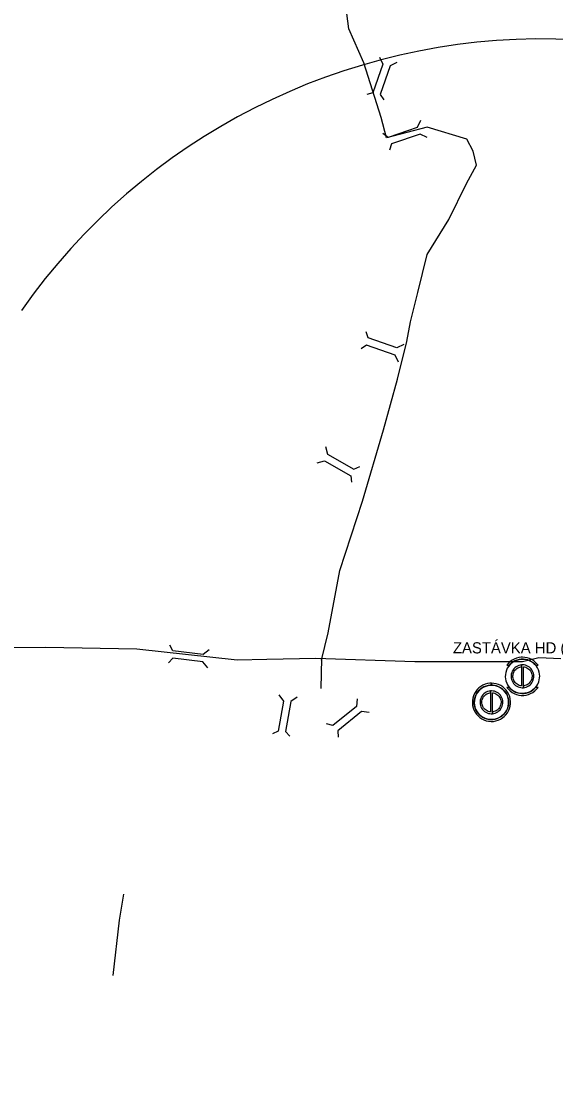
# Model space of a CAD drawing. Extents: x -520790 to -517278, y -1190021 to -1185077.
# Drawn here: x -519098 to -518762, y -1187441 to -1186765 of the extents above; entities that cross this region are included whole.
import ezdxf

# ---------------------------------------------------------------- set-up
doc = ezdxf.new("R2010")
doc.units = 0
for name, color, linetype in [('cyklostezka_n', 7, 'Continuous'), ('cyklostezka_s', 7, 'Continuous'), ('dostupnost_s', 7, 'Continuous'), ('most_s', 7, 'Continuous'), ('stezka_s', 7, 'Continuous'), ('zast_HD_n', 7, 'Continuous'), ('zast_HD_s', 7, 'Continuous')]:
    doc.layers.add(name, color=color, linetype=linetype)

msp = doc.modelspace()

# ---------------------------------------------------------------- linework, layer by layer
at = {"layer": 'cyklostezka_n'}
msp.add_lwpolyline([(-518909.06, -1187166.39), (-518904.87, -1187149.27), (-518897.53, -1187110.14), (-518883.2, -1187066.46), (-518870.1, -1187021.73), (-518861.36, -1186989.94), (-518855.42, -1186966.18), (-518853.15, -1186953.95), (-518848.44, -1186935.43), (-518842.67, -1186911.67), (-518829.04, -1186889.65), (-518817.86, -1186866.94), (-518811.57, -1186855.41), (-518813.67, -1186846.67), (-518817.7, -1186839.01), (-518842.67, -1186831.65), (-518868.09, -1186838.24), (-518871.57, -1186825.5), (-518882.5, -1186791.12), (-518891.94, -1186769.8), (-518895.08, -1186745.52)], dxfattribs=at)
at = {"layer": 'cyklostezka_s'}
msp.add_lwpolyline([(-519148.5, -1187158.48), (-519082.51, -1187158.33), (-519025.1, -1187159.41), (-518962.02, -1187166.21), (-518943.49, -1187165.91), (-518912.67, -1187165.14), (-518850.44, -1187167.37), (-518782.75, -1187167.37), (-518772.35, -1187164.69), (-518758.64, -1187165.51)], dxfattribs=at)
at = {"layer": 'dostupnost_s'}
for centre, start, end in [((-518769.97, -1187176.11), 32.65634, 144.99756), ((-519122.18, -1187345.91), 185.51814, 324.99756)]:
    msp.add_arc(centre, 400, start, end, dxfattribs=at)
at = {"layer": 'most_s'}
for points in [[(-518872.6, -1186787.54), (-518870.47, -1186791.9), (-518876.69, -1186809.95), (-518880.6, -1186811.14)], [(-518861.59, -1186790.87), (-518865.97, -1186792.97), (-518872.26, -1186811), (-518869.93, -1186814.34)], [(-518846.89, -1186827.35), (-518849, -1186831.72), (-518867.05, -1186837.97), (-518870.39, -1186835.63)], [(-518842.71, -1186838.07), (-518847.06, -1186835.92), (-518865.13, -1186842.1), (-518866.33, -1186846)], [(-518857.3, -1186968.12), (-518861.65, -1186970.26), (-518879.71, -1186964.03), (-518880.89, -1186960.13)], [(-518860.62, -1186979.13), (-518862.72, -1186974.76), (-518880.75, -1186968.46), (-518884.1, -1186970.8)], [(-518906.54, -1187032.27), (-518905.29, -1187036.95), (-518888.74, -1187046.49), (-518885.01, -1187044.81)], [(-518911.85, -1187042.47), (-518907.17, -1187041.18), (-518890.58, -1187050.65), (-518890.15, -1187054.71)], [(-518979.66, -1187159.89), (-518983.46, -1187162.9), (-519002.43, -1187160.65), (-519004.41, -1187157.08)], [(-518980.57, -1187171.35), (-518983.55, -1187167.52), (-519002.5, -1187165.2), (-519005.28, -1187168.19)], [(-518935.82, -1187188.23), (-518933.01, -1187192.18), (-518936.24, -1187211), (-518939.91, -1187212.8)], [(-518924.42, -1187189.73), (-518928.4, -1187192.51), (-518931.7, -1187211.32), (-518928.86, -1187214.24)], [(-518886.65, -1187190.68), (-518887.14, -1187195.51), (-518901.95, -1187207.56), (-518905.89, -1187206.5)], [(-518879.05, -1187199.32), (-518883.87, -1187198.79), (-518898.74, -1187210.78), (-518898.52, -1187214.86)]]:
    msp.add_lwpolyline(points, dxfattribs=at)
at = {"layer": 'stezka_s'}
for points in [[(-518909, -1187165.33), (-518909.41, -1187184.23), (-518909.41, -1187184.23)], [(-519039.9, -1187364.57), (-519036.07, -1187329.87), (-519033.21, -1187313.42)]]:
    msp.add_lwpolyline(points, dxfattribs=at)
at = {"layer": 'zast_HD_n'}
msp.add_line((-518782.09, -1187183.76), (-518782.09, -1187183.76), dxfattribs=at)
for points in [[(-518771.89, -1187176.6), (-518771.98, -1187175.23), (-518772.24, -1187173.89), (-518772.66, -1187172.59), (-518773.25, -1187171.36), (-518773.98, -1187170.21), (-518774.86, -1187169.16), (-518775.86, -1187168.23), (-518776.97, -1187167.43), (-518778.17, -1187166.78), (-518779.45, -1187166.29), (-518780.77, -1187165.96), (-518782.13, -1187165.81), (-518783.5, -1187165.82), (-518784.85, -1187166.01), (-518786.17, -1187166.36), (-518787.43, -1187166.88), (-518788.62, -1187167.56), (-518789.72, -1187168.38), (-518790.7, -1187169.33), (-518791.55, -1187170.4), (-518792.26, -1187171.56), (-518792.82, -1187172.81), (-518793.22, -1187174.12), (-518793.45, -1187175.46), (-518793.51, -1187176.83), (-518793.39, -1187178.19), (-518793.1, -1187179.53), (-518792.65, -1187180.81), (-518792.04, -1187182.04), (-518791.28, -1187183.17), (-518790.38, -1187184.2), (-518789.36, -1187185.11), (-518788.23, -1187185.88), (-518787.02, -1187186.51), (-518785.73, -1187186.97), (-518784.4, -1187187.27), (-518783.04, -1187187.4), (-518781.67, -1187187.36), (-518780.32, -1187187.14), (-518779.01, -1187186.76), (-518777.76, -1187186.21), (-518776.59, -1187185.51), (-518775.51, -1187184.67), (-518774.55, -1187183.7), (-518773.72, -1187182.61), (-518773.03, -1187181.43), (-518772.5, -1187180.17), (-518772.13, -1187178.86), (-518771.93, -1187177.51), (-518771.89, -1187176.6)], [(-518782.71, -1187164.59), (-518783.46, -1187164.61), (-518784.97, -1187164.81), (-518786.44, -1187165.18), (-518787.85, -1187165.75), (-518789.18, -1187166.48), (-518790.4, -1187167.38), (-518791.5, -1187168.42), (-518792.47, -1187169.6)], [(-518790.94, -1187169.6), (-518790.15, -1187168.76), (-518789.1, -1187167.88), (-518787.95, -1187167.15), (-518786.72, -1187166.56), (-518785.42, -1187166.14), (-518784.08, -1187165.88), (-518782.71, -1187165.79)], [(-518772.95, -1187169.6), (-518773.41, -1187169), (-518774.44, -1187167.89), (-518775.61, -1187166.92), (-518776.88, -1187166.1), (-518778.26, -1187165.45), (-518779.7, -1187164.97), (-518781.19, -1187164.69), (-518782.7, -1187164.59)], [(-518782.7, -1187165.79), (-518781.55, -1187165.85), (-518780.21, -1187166.08), (-518778.9, -1187166.48), (-518777.65, -1187167.05), (-518776.49, -1187167.76), (-518775.42, -1187168.62), (-518774.47, -1187169.6)], [(-518792.47, -1187169.6), (-518790.94, -1187169.6)], [(-518783.33, -1187169.44), (-518784.23, -1187169.57), (-518785.1, -1187169.82), (-518785.94, -1187170.18), (-518786.72, -1187170.64), (-518787.44, -1187171.19), (-518788.09, -1187171.83), (-518788.65, -1187172.55), (-518789.11, -1187173.33), (-518789.47, -1187174.17), (-518789.73, -1187175.04), (-518789.86, -1187175.94), (-518789.89, -1187176.84), (-518789.8, -1187177.75), (-518789.6, -1187178.63), (-518789.29, -1187179.49), (-518788.87, -1187180.3), (-518788.36, -1187181.04), (-518787.75, -1187181.72), (-518787.06, -1187182.32), (-518786.31, -1187182.82), (-518785.5, -1187183.22), (-518784.64, -1187183.52), (-518783.75, -1187183.71), (-518782.84, -1187183.78), (-518782.13, -1187183.76)], [(-518783.28, -1187182.61), (-518784.04, -1187182.49), (-518784.77, -1187182.27), (-518785.47, -1187181.97), (-518786.13, -1187181.58), (-518786.73, -1187181.11), (-518787.26, -1187180.56), (-518787.73, -1187179.96), (-518788.11, -1187179.3), (-518788.41, -1187178.59), (-518788.61, -1187177.86), (-518788.72, -1187177.1), (-518788.74, -1187176.34), (-518788.66, -1187175.58), (-518788.48, -1187174.84), (-518788.22, -1187174.12), (-518787.86, -1187173.45), (-518787.42, -1187172.82), (-518786.91, -1187172.26), (-518786.33, -1187171.76), (-518785.69, -1187171.35), (-518785, -1187171.01), (-518784.28, -1187170.77), (-518783.53, -1187170.62), (-518783.33, -1187170.59)], [(-518783.33, -1187170.59), (-518783.33, -1187169.44)], [(-518782.09, -1187183.76), (-518781.19, -1187183.62), (-518780.31, -1187183.38), (-518779.48, -1187183.02), (-518778.69, -1187182.56), (-518777.97, -1187182.01), (-518777.33, -1187181.36), (-518776.77, -1187180.65), (-518776.31, -1187179.87), (-518775.95, -1187179.03), (-518775.69, -1187178.16), (-518775.55, -1187177.26), (-518775.53, -1187176.35), (-518775.61, -1187175.45), (-518775.82, -1187174.56), (-518776.13, -1187173.71), (-518776.54, -1187172.9), (-518777.06, -1187172.15), (-518777.67, -1187171.48), (-518778.35, -1187170.88), (-518779.11, -1187170.38), (-518779.92, -1187169.97), (-518780.78, -1187169.67), (-518781.67, -1187169.49), (-518782.58, -1187169.41), (-518783.28, -1187169.43)], [(-518783.28, -1187169.43), (-518783.28, -1187182.61)], [(-518782.13, -1187183.76), (-518782.13, -1187170.59)], [(-518782.13, -1187170.59), (-518781.38, -1187170.71), (-518780.65, -1187170.92), (-518779.95, -1187171.23), (-518779.29, -1187171.62), (-518778.69, -1187172.09), (-518778.16, -1187172.63), (-518777.69, -1187173.24), (-518777.31, -1187173.9), (-518777.01, -1187174.6), (-518776.8, -1187175.34), (-518776.69, -1187176.09), (-518776.68, -1187176.86), (-518776.76, -1187177.62), (-518776.93, -1187178.36), (-518777.2, -1187179.07), (-518777.56, -1187179.75), (-518778, -1187180.37), (-518778.51, -1187180.94), (-518779.09, -1187181.43), (-518779.73, -1187181.85), (-518780.42, -1187182.18), (-518781.14, -1187182.43), (-518781.89, -1187182.58), (-518782.09, -1187182.6)], [(-518774.47, -1187169.6), (-518772.95, -1187169.6)], [(-518782.09, -1187182.6), (-518782.09, -1187183.76)], [(-518792.47, -1187183.6), (-518791.51, -1187184.77), (-518790.41, -1187185.81), (-518789.19, -1187186.71), (-518787.86, -1187187.45), (-518786.45, -1187188.01), (-518784.98, -1187188.39), (-518783.47, -1187188.58), (-518781.96, -1187188.58), (-518780.45, -1187188.39), (-518778.98, -1187188.01), (-518777.57, -1187187.45), (-518776.24, -1187186.72), (-518775.02, -1187185.82), (-518773.91, -1187184.77), (-518772.95, -1187183.6)], [(-518790.94, -1187183.6), (-518792.47, -1187183.6)], [(-518774.47, -1187183.6), (-518775.12, -1187184.29), (-518776.15, -1187185.19), (-518777.29, -1187185.95), (-518778.51, -1187186.56), (-518779.8, -1187187.01), (-518781.14, -1187187.29), (-518782.5, -1187187.4), (-518783.87, -1187187.34), (-518785.21, -1187187.11), (-518786.52, -1187186.71), (-518787.76, -1187186.15), (-518788.93, -1187185.44), (-518790, -1187184.58), (-518790.94, -1187183.6)], [(-518772.95, -1187183.6), (-518774.47, -1187183.6)]]:
    msp.add_lwpolyline(points, dxfattribs=at)
at = {"layer": 'zast_HD_s'}
msp.add_line((-518801.59, -1187200.11), (-518801.59, -1187200.11), dxfattribs=at)
for points in [[(-518802.22, -1187180.94), (-518803.22, -1187180.99), (-518804.72, -1187181.21), (-518806.18, -1187181.62), (-518807.58, -1187182.21), (-518808.89, -1187182.97), (-518810.1, -1187183.9), (-518811.18, -1187184.96), (-518812.11, -1187186.16), (-518812.89, -1187187.46), (-518813.5, -1187188.85), (-518813.93, -1187190.31), (-518814.17, -1187191.81), (-518814.21, -1187193.32), (-518814.07, -1187194.84), (-518813.74, -1187196.32), (-518813.22, -1187197.75), (-518812.53, -1187199.1), (-518811.67, -1187200.35), (-518810.66, -1187201.48), (-518809.52, -1187202.48), (-518808.26, -1187203.33), (-518806.9, -1187204.01), (-518805.47, -1187204.51), (-518803.98, -1187204.83), (-518802.47, -1187204.96), (-518800.96, -1187204.89), (-518799.46, -1187204.64), (-518798.01, -1187204.2), (-518796.62, -1187203.58), (-518795.32, -1187202.79), (-518794.14, -1187201.84), (-518793.08, -1187200.75), (-518792.17, -1187199.54), (-518791.42, -1187198.22), (-518790.84, -1187196.81), (-518790.45, -1187195.35), (-518790.24, -1187193.84), (-518790.22, -1187192.33), (-518790.4, -1187190.82), (-518790.76, -1187189.34), (-518791.31, -1187187.93), (-518792.03, -1187186.59), (-518792.91, -1187185.36), (-518793.94, -1187184.24), (-518795.11, -1187183.27), (-518796.39, -1187182.45), (-518797.76, -1187181.8), (-518799.2, -1187181.33), (-518800.69, -1187181.04), (-518802.21, -1187180.94)], [(-518791.4, -1187192.95), (-518791.49, -1187191.59), (-518791.75, -1187190.25), (-518792.17, -1187188.95), (-518792.76, -1187187.71), (-518793.5, -1187186.56), (-518794.37, -1187185.51), (-518795.37, -1187184.58), (-518796.48, -1187183.79), (-518797.69, -1187183.14), (-518798.96, -1187182.65), (-518800.29, -1187182.32), (-518801.64, -1187182.16), (-518803.01, -1187182.17), (-518804.36, -1187182.36), (-518805.68, -1187182.72), (-518806.95, -1187183.24), (-518808.13, -1187183.91), (-518809.23, -1187184.73), (-518810.21, -1187185.68), (-518811.06, -1187186.75), (-518811.77, -1187187.92), (-518812.33, -1187189.16), (-518812.73, -1187190.47), (-518812.96, -1187191.82), (-518813.02, -1187193.18), (-518812.9, -1187194.54), (-518812.62, -1187195.88), (-518812.16, -1187197.17), (-518811.55, -1187198.39), (-518810.79, -1187199.53), (-518809.89, -1187200.56), (-518808.87, -1187201.46), (-518807.75, -1187202.24), (-518806.53, -1187202.86), (-518805.25, -1187203.33), (-518803.91, -1187203.63), (-518802.55, -1187203.76), (-518801.19, -1187203.71), (-518799.84, -1187203.5), (-518798.53, -1187203.11), (-518797.27, -1187202.57), (-518796.1, -1187201.87), (-518795.02, -1187201.02), (-518794.06, -1187200.05), (-518793.23, -1187198.97), (-518792.55, -1187197.79), (-518792.01, -1187196.53), (-518791.64, -1187195.21), (-518791.44, -1187193.86), (-518791.4, -1187192.95)], [(-518802.21, -1187182.14), (-518801.31, -1187182.18), (-518799.96, -1187182.38), (-518798.64, -1187182.75), (-518797.38, -1187183.28), (-518796.2, -1187183.97), (-518795.12, -1187184.8), (-518794.15, -1187185.76), (-518793.3, -1187186.84), (-518792.6, -1187188.01), (-518792.05, -1187189.26), (-518791.67, -1187190.57), (-518791.45, -1187191.92), (-518791.41, -1187193.29), (-518791.54, -1187194.65), (-518791.84, -1187195.98), (-518792.3, -1187197.27), (-518792.93, -1187198.48), (-518793.7, -1187199.61), (-518794.61, -1187200.63), (-518795.64, -1187201.53), (-518796.77, -1187202.29), (-518797.99, -1187202.9), (-518799.28, -1187203.36), (-518800.62, -1187203.64), (-518801.98, -1187203.76), (-518803.34, -1187203.7), (-518804.69, -1187203.47), (-518806, -1187203.08), (-518807.25, -1187202.52), (-518808.41, -1187201.81), (-518809.48, -1187200.95), (-518810.43, -1187199.97), (-518811.25, -1187198.88), (-518811.93, -1187197.69), (-518812.45, -1187196.43), (-518812.8, -1187195.11), (-518812.99, -1187193.76), (-518813.01, -1187192.39), (-518812.85, -1187191.03), (-518812.52, -1187189.7), (-518812.03, -1187188.43), (-518811.38, -1187187.23), (-518810.58, -1187186.12), (-518809.65, -1187185.12), (-518808.61, -1187184.24), (-518807.46, -1187183.5), (-518806.22, -1187182.92), (-518804.92, -1187182.49), (-518803.58, -1187182.23), (-518802.22, -1187182.14)], [(-518802.22, -1187182.14), (-518802.22, -1187180.94)], [(-518802.21, -1187180.94), (-518802.21, -1187182.14)], [(-518802.83, -1187185.79), (-518803.73, -1187185.93), (-518804.61, -1187186.18), (-518805.44, -1187186.53), (-518806.23, -1187186.99), (-518806.95, -1187187.55), (-518807.59, -1187188.19), (-518808.15, -1187188.9), (-518808.61, -1187189.68), (-518808.98, -1187190.52), (-518809.23, -1187191.39), (-518809.37, -1187192.29), (-518809.4, -1187193.2), (-518809.31, -1187194.1), (-518809.1, -1187194.99), (-518808.79, -1187195.84), (-518808.38, -1187196.65), (-518807.86, -1187197.4), (-518807.25, -1187198.08), (-518806.57, -1187198.67), (-518805.81, -1187199.17), (-518805, -1187199.58), (-518804.14, -1187199.88), (-518803.25, -1187200.06), (-518802.35, -1187200.14), (-518801.64, -1187200.12)], [(-518802.79, -1187198.96), (-518803.54, -1187198.84), (-518804.27, -1187198.63), (-518804.97, -1187198.32), (-518805.63, -1187197.93), (-518806.23, -1187197.46), (-518806.76, -1187196.92), (-518807.23, -1187196.31), (-518807.61, -1187195.65), (-518807.91, -1187194.95), (-518808.12, -1187194.21), (-518808.23, -1187193.46), (-518808.24, -1187192.69), (-518808.16, -1187191.94), (-518807.99, -1187191.19), (-518807.72, -1187190.48), (-518807.36, -1187189.8), (-518806.92, -1187189.18), (-518806.41, -1187188.61), (-518805.83, -1187188.12), (-518805.19, -1187187.7), (-518804.5, -1187187.37), (-518803.78, -1187187.12), (-518803.03, -1187186.97), (-518802.83, -1187186.95)], [(-518802.83, -1187186.95), (-518802.83, -1187185.79)], [(-518801.59, -1187200.11), (-518800.69, -1187199.98), (-518799.82, -1187199.73), (-518798.98, -1187199.37), (-518798.2, -1187198.91), (-518797.48, -1187198.36), (-518796.83, -1187197.72), (-518796.27, -1187197), (-518795.81, -1187196.22), (-518795.45, -1187195.39), (-518795.2, -1187194.51), (-518795.06, -1187193.62), (-518795.03, -1187192.71), (-518795.12, -1187191.8), (-518795.32, -1187190.92), (-518795.63, -1187190.06), (-518796.05, -1187189.26), (-518796.56, -1187188.51), (-518797.17, -1187187.83), (-518797.86, -1187187.24), (-518798.61, -1187186.73), (-518799.43, -1187186.33), (-518800.28, -1187186.03), (-518801.17, -1187185.84), (-518802.08, -1187185.77), (-518802.79, -1187185.79)], [(-518802.79, -1187185.79), (-518802.79, -1187198.96)], [(-518801.64, -1187200.12), (-518801.64, -1187186.94)], [(-518801.64, -1187186.94), (-518800.88, -1187187.06), (-518800.15, -1187187.28), (-518799.45, -1187187.58), (-518798.8, -1187187.97), (-518798.2, -1187188.45), (-518797.66, -1187188.99), (-518797.19, -1187189.6), (-518796.81, -1187190.25), (-518796.51, -1187190.96), (-518796.31, -1187191.69), (-518796.2, -1187192.45), (-518796.18, -1187193.21), (-518796.26, -1187193.97), (-518796.44, -1187194.71), (-518796.7, -1187195.43), (-518797.06, -1187196.1), (-518797.5, -1187196.73), (-518798.01, -1187197.29), (-518798.59, -1187197.79), (-518799.23, -1187198.2), (-518799.92, -1187198.54), (-518800.64, -1187198.78), (-518801.39, -1187198.93), (-518801.59, -1187198.96)], [(-518801.59, -1187198.96), (-518801.59, -1187200.11)]]:
    msp.add_lwpolyline(points, dxfattribs=at)

# ---------------------------------------------------------------- texts
at = {"layer": 'zast_HD_n'}
msp.add_text('ZASTÁVKA HD (NÁVRH)', height=7, dxfattribs=at).set_placement((-518826.45, -1187162.2))

doc.saveas('drawing.dxf')
